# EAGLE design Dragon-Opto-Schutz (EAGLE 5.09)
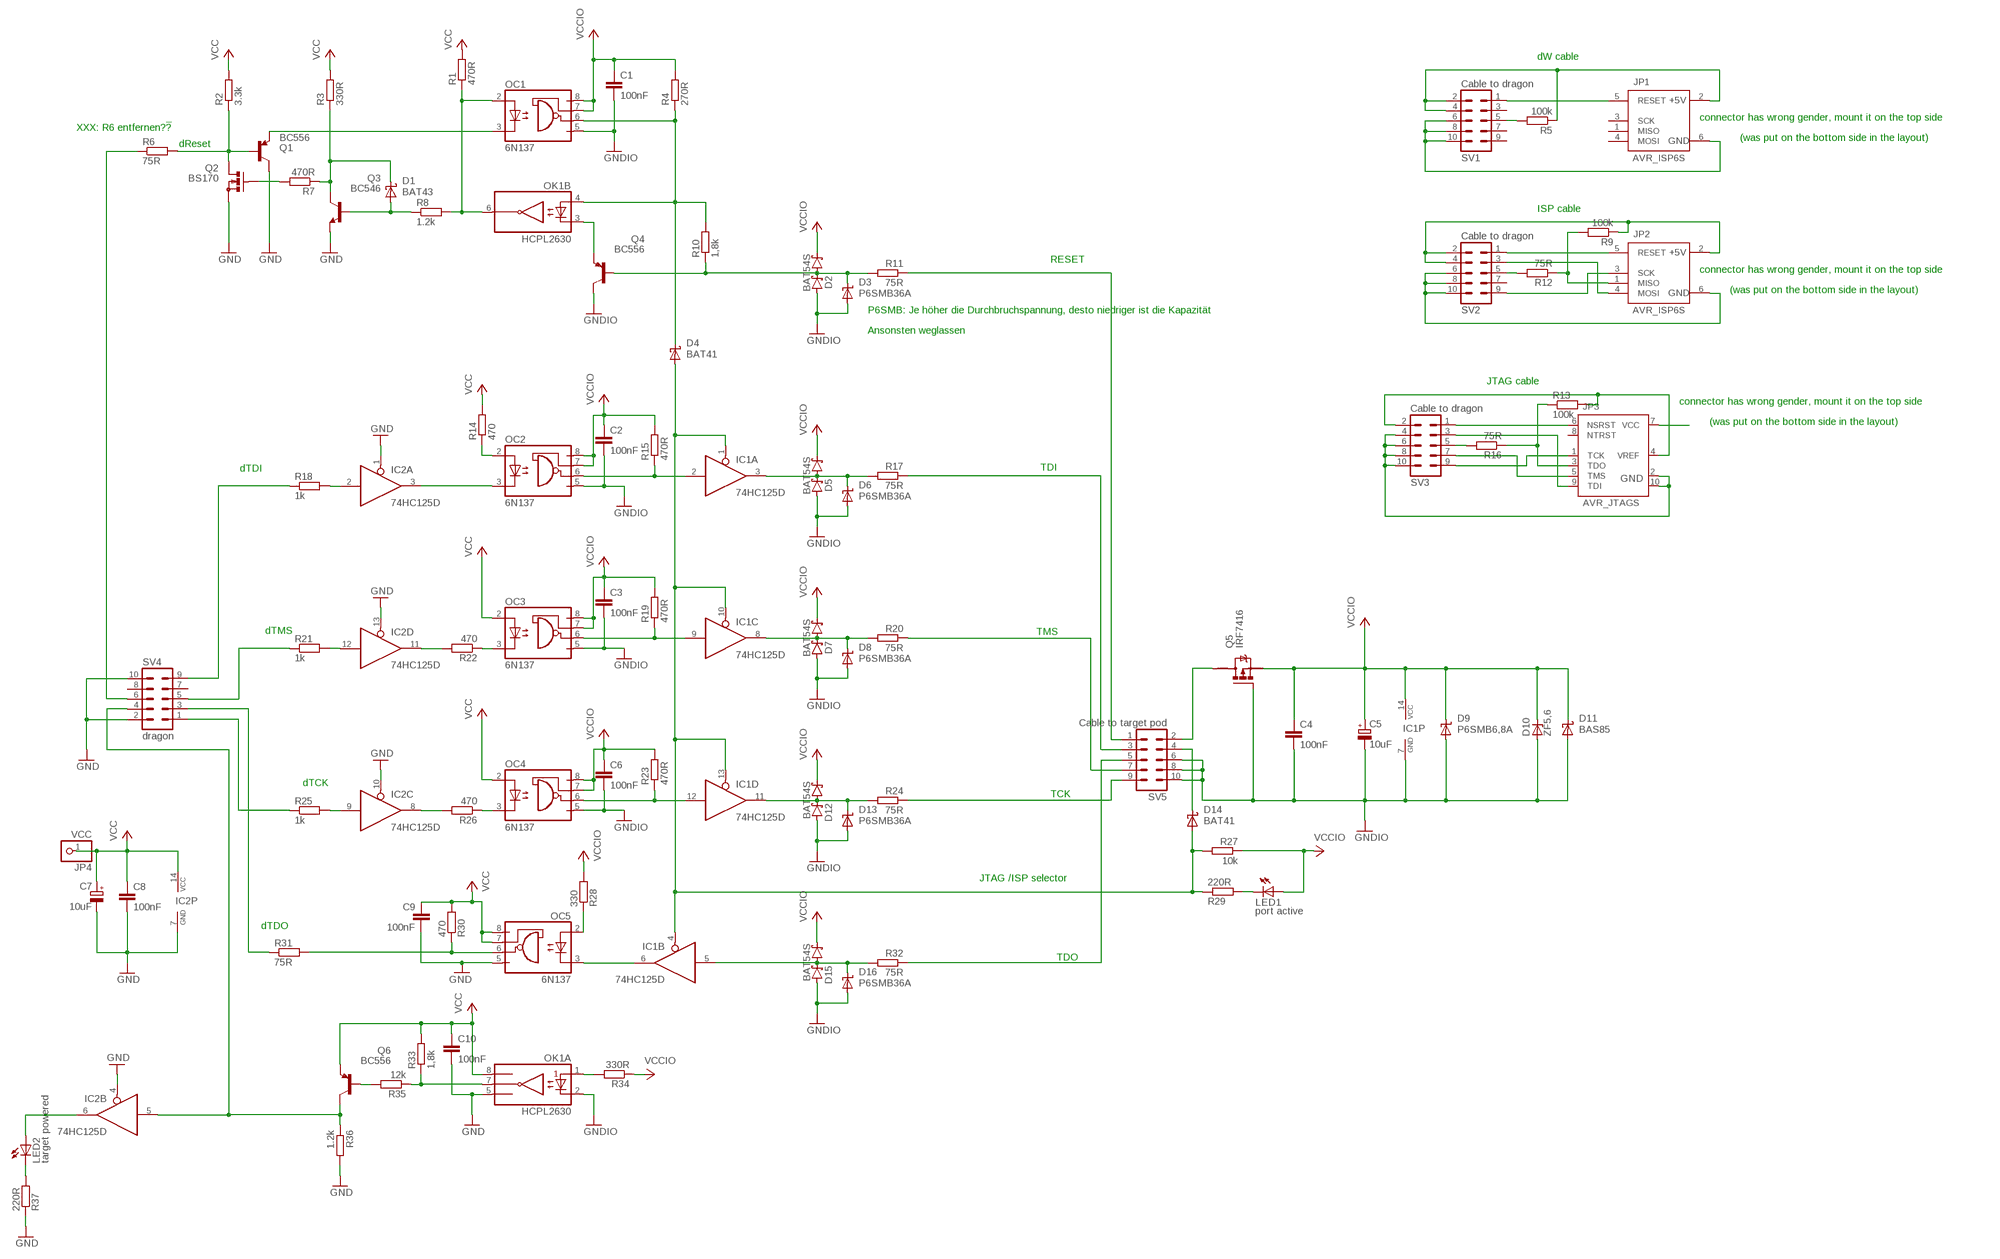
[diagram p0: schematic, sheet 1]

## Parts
C1  100nF  C-EUC0805  [C0805]
C2  100nF  C-EUC0805  [C0805]
C3  100nF  C-EUC0805  [C0805]
C4  100nF  C-EUC0805  [C0805]
C5  10uF  CPOL-EUB  [PANASONIC_B]
C6  100nF  C-EUC0805  [C0805]
C7  10uF  CPOL-EUB  [PANASONIC_B]
C8  100nF  C-EUC0805  [C0805]
C9  100nF  C-EUC0805  [C0805]
C10  100nF  C-EUC0805  [C0805]
D1  BAT43  SCHOTTKY-MINIMELF  [MINIMELF]
D2  BAT54S  DUAL_SCHOTTKY_CACASOT23  [SOT23]
D3  P6SMB36A  P6SMBXXA  [SMB]
D4  BAT41  SCHOTTKY-MINIMELF  [MINIMELF]
D5  BAT54S  DUAL_SCHOTTKY_CACASOT23  [SOT23]
D6  P6SMB36A  P6SMBXXA  [SMB]
D7  BAT54S  DUAL_SCHOTTKY_CACASOT23  [SOT23]
D8  P6SMB36A  P6SMBXXA  [SMB]
D9  P6SMB6,8A  P6SMBXXA  [SMB]
D10  ZF5,6  ZENER-SMD  [MINIMELF]
D11  BAS85  SCHOTTKY-SOD80  [SOD80C]
D12  BAT54S  DUAL_SCHOTTKY_CACASOT23  [SOT23]
D13  P6SMB36A  P6SMBXXA  [SMB]
D14  BAT41  SCHOTTKY-MINIMELF  [MINIMELF]
D15  BAT54S  DUAL_SCHOTTKY_CACASOT23  [SOT23]
D16  P6SMB36A  P6SMBXXA  [SMB]
IC1  74HC125D  [SO14]
IC2  74HC125D  [SO14]
JP1  AVR_ISP6S  [LEISTE_2X03]
JP2  AVR_ISP6S  [LEISTE_2X03]
JP3  AVR_JTAGS  [LEISTE_2X05]
JP4  VCC  PINHD-1X1  [1X01]
LED1  port active  LED3MM  [LED3MM]
LED2  target powered  LED3MM  [LED3MM]
OC1  6N137  [DIL08]
OC2  6N137  [DIL08]
OC3  6N137  [DIL08]
OC4  6N137  [DIL08]
OC5  6N137  [DIL08]
OK1  HCPL2630  [DIL08]
Q1  BC556  [TO92-EBC]
Q2  BS170  [SOT54E]
Q3  BC546  BC546B  [TO92-EBC]
Q4  BC556  [TO92-EBC]
Q5  IRF7416  P-MOSFET-SO8  [SO-08]
Q6  BC556  [TO92-EBC]
R1  470R  R-EU_R1206  [R1206]
R2  3.3k  R-EU_R0805  [R0805]
R3  330R  R-EU_R1206  [R1206]
R4  270R  R-EU_R1206  [R1206]
R5  100k  R-EU_R0805  [R0805]
R6  75R  R-EU_R1206  [R1206]
R7  470R  R-EU_R1206  [R1206]
R8  1.2k  R-EU_R0805  [R0805]
R9  100k  R-EU_R0805  [R0805]
R10  1,8k  R-EU_R0805  [R0805]
R11  75R  R-EU_R1206  [R1206]
R12  75R  R-EU_R1206  [R1206]
R13  100k  R-EU_R0805  [R0805]
R14  470  R-EU_R1206  [R1206]
R15  470R  R-EU_R1206  [R1206]
R16  75R  R-EU_R1206  [R1206]
R17  75R  R-EU_R1206  [R1206]
R18  1k  R-EU_R0805  [R0805]
R19  470R  R-EU_R1206  [R1206]
R20  75R  R-EU_R1206  [R1206]
R21  1k  R-EU_R0805  [R0805]
R22  470  R-EU_R1206  [R1206]
R23  470R  R-EU_R1206  [R1206]
R24  75R  R-EU_R1206  [R1206]
R25  1k  R-EU_R0805  [R0805]
R26  470  R-EU_R1206  [R1206]
R27  10k  R-EU_R0805  [R0805]
R28  330  R-EU_R1206  [R1206]
R29  220R  R-EU_R1206  [R1206]
R30  470  R-EU_R1206  [R1206]
R31  75R  R-EU_R1206  [R1206]
R32  75R  R-EU_R1206  [R1206]
R33  1,8k  R-EU_R0805  [R0805]
R34  330R  R-EU_R1206  [R1206]
R35  12k  R-EU_R0805  [R0805]
R36  1.2k  R-EU_R0805  [R0805]
R37  220R  R-EU_R1206  [R1206]
SV1  Cable to dragon  MA05-2  [MA05-2]
SV2  Cable to dragon  MA05-2  [MA05-2]
SV3  Cable to dragon  MA05-2  [MA05-2]
SV4  dragon  MA05-2  [MA05-2]
SV5  Cable to target pod  MA05-2  [MA05-2]

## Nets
GND: C7.- C8.2 C9.2 C10.2 IC2.1(A:OE) IC2.4(B:OE) IC2.7(P:GND) IC2.10(C:OE) IC2.13(D:OE) OC5.5(GND) OK1.5(A:GND) Q1.C Q2.S Q3.E R36.2 R37.1 SV4.2 SV4.10
GNDIO: C1.2 C2.2 C3.2 C4.2 C5.- C6.2 D2.1(A) D3.A D5.1(A) D6.A D7.1(A) D8.A D9.A D10.A D11.A D12.1(A) D13.A D15.1(A) D16.A IC1.7(P:GND) OC1.5(GND) OC2.5(GND) OC3.5(GND) OC4.5(GND) OK1.2(A:C1) Q4.C Q5.4(G) SV5.6 SV5.8 SV5.10
JT_TCK: R24.1 SV5.9
JT_TDO: R32.1 SV5.5
JT_TMS: R20.1 SV5.7
MISO_TDO: OC5.6(VO) R30.1 R31.2
MOSI_TDI: IC2.3(A:O) OC2.3(C)
N$1: Q5.5(D) SV5.2
N$2: IC2.2(A:I) R18.2
N$3: IC2.12(D:I) R21.2
N$4: IC2.9(C:I) R25.2
N$5: LED2.K(C) R37.2
N$6: JP1.2(+5V) R5.1 SV1.2 SV1.4
N$7: D2.3(AC) D3.C Q4.B R10.1 R11.2
N$8: R17.1 SV5.3
N$9: IC2.6(B:O) LED2.A
N$10: D4.C OC1.6(VO) OK1.4(B:A2) R4.1 R10.2
N$11: LED1.K(C) R29.2
N$12: D14.C SV5.4
N$13: R6.1 SV4.6
N$14: R11.1 SV5.1
N$15: OK1.1(A:A1) R34.2
N$16: R25.1 SV4.1
N$17: JP2.2(+5V) R9.1 SV2.2 SV2.4
N$18: JP2.6(GND) SV2.6 SV2.8 SV2.10
N$19: R18.1 SV4.9
N$20: R21.1 SV4.5
N$21: R31.1 SV4.3
N$22: JP3.4(VREF) R13.2 SV3.2
N$23: JP3.2(GND) JP3.10(GND) SV3.4 SV3.6 SV3.8 SV3.10
N$24: JP3.3(TDO) R13.1 R16.1
N$25: R16.2 SV3.5
N$26: JP3.6(NSRST) SV3.1
N$27: JP3.9(TDI) SV3.3
N$28: JP3.5(TMS) SV3.7
N$29: JP3.1(TCK) SV3.9
N$30: JP2.3(SCK) SV2.9
N$31: JP2.4(MOSI) SV2.3
N$32: JP2.1(MISO) R9.2 R12.1
N$33: R12.2 SV2.5
N$34: JP2.5(RESET) SV2.1
N$35: D4.A D14.A IC1.1(A:OE) IC1.4(B:OE) IC1.10(C:OE) IC1.13(D:OE) R27.2 R29.1
N$36: JP1.6(GND) SV1.6 SV1.8 SV1.10
N$37: R5.2 SV1.5
N$38: OC5.2(A) R28.1
N$39: OC2.2(A) R14.1
N$40: IC1.2(A:I) OC2.6(VO) R15.1
N$41: JP1.5(RESET) SV1.1
N$42: JP3.7(VCC)
N$43: IC1.9(C:I) OC3.6(VO) R19.1
N$45: IC1.12(D:I) OC4.6(VO) R23.1
N$46: D5.3(AC) D6.C IC1.3(A:O) R17.2
N$47: D7.3(AC) D8.C IC1.8(C:O) R20.2
N$48: D12.3(AC) D13.C IC1.11(D:O) R24.2
N$49: D15.3(AC) D16.C IC1.5(B:I) R32.2
N$50: IC1.6(B:O) OC5.3(C)
N$51: OK1.7(A:VO1) R33.1 R35.1
N$52: Q6.B R35.2
N$53: OC1.3(C) Q1.E
N$54: D1.A Q3.B R8.1
N$55: D1.C Q3.C R3.1 R7.1
N$56: Q2.G R7.2
N$57: Q1.B Q2.D R2.1 R6.2
N$58: IC2.8(C:O) R26.2
N$59: OC1.2(A) OK1.6(B:VO2) R1.1 R8.2
N$60: IC2.5(B:I) Q6.C R36.1 SV4.4
N$61: OK1.3(B:C2) Q4.E
N$62: OC4.3(C) R26.1
N$63: IC2.11(D:O) R22.2
N$64: OC3.3(C) R22.1
VCC: C7.+ C8.1 C9.1 C10.1 IC2.14(P:VCC) JP4.1 OC3.2(A) OC4.2(A) OC5.7(VE) OC5.8(VCC) OK1.8(A:VCC) Q6.E R1.2 R2.2 R3.2 R14.2 R30.2 R33.2
VCCIO: C1.1 C2.1 C3.1 C4.1 C5.+ C6.1 D2.2(C) D5.2(C) D7.2(C) D9.C D10.C D11.C D12.2(C) D15.2(C) IC1.14(P:VCC) LED1.A OC1.7(VE) OC1.8(VCC) OC2.7(VE) OC2.8(VCC) OC3.7(VE) OC3.8(VCC) OC4.7(VE) OC4.8(VCC) Q5.1(S) R4.2 R15.2 R19.2 R23.2 R27.1 R28.2 R34.1
Unconnected: JP1.1(MISO) JP1.3(SCK) JP1.4(MOSI) JP3.8(NTRST) Q5.2(S) Q5.3(S) Q5.6(D) Q5.7(D) Q5.8(D) SV1.3 SV1.7 SV1.9 SV2.7 SV4.7 SV4.8

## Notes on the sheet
- dW cable
- connector has wrong gender, mount it on the top side
- XXX: R6 entfernen?!?
- (was put on the bottom side in the layout)
- dReset
- ISP cable
- RESET
- connector has wrong gender, mount it on the top side
- (was put on the bottom side in the layout)
- P6SMB: Je höher die Durchbruchspannung, desto niedriger ist die Kapazität
- Ansonsten weglassen
- JTAG cable
- connector has wrong gender, mount it on the top side
- (was put on the bottom side in the layout)
- dTDI | TDI
- dTMS | TMS
- dTCK
- TCK
- JTAG /ISP selector
- dTDO
- TDO

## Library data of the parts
C1-C4 C6 C8-C10 = thomas4:C-EU: CAPACITOR, European symbol
C5 C7 = thomas4:CPOL-EU: POLARIZED CAPACITOR, European symbol
D1 D4 D11 D14 = 11my-ICs:SCHOTTKY-
D2 D5 D7 D12 D15 = Thomas2:DUAL_SCHOTTKY_CACA: 2 Diodes - Cathode-Anode|Cathode-Anode
D3 D6 D8 D9 D13 D16 = 11my-ICs:P6SMBXXA: Suppressor diode
D10 = 11my-ICs:ZENER-SMD: Z DIODE
IC1 IC2 = thomas-74:74*125: Quad bus BUFFER, 3-state
JP1 JP2 = 11my-AVR:AVR_ISP6: ISP (In System Programming) Stecker fr AVRs ber diesen Anschlu kann ein AVR mit einem Standard ISP-Kabel direkt an einen Parallelport des PCs angeschlossen und programmiert werden.
JP3 = 11my-AVR:AVR_JTAG: AVR JTAG Adapter Zum Programmieren/Simulieren von AVRs in der Schaltung
JP4 = pinhead:PINHD-1X1: PIN HEADER
LED1 LED2 = led:LED: LED
OC1-OC5 = thomas5:6N137: MOTOROLA OPTO COUPLER
OK1 = optocoupler:HCPL2630: HEWLETT PACKARD OPTO COUPLER
Q1 Q4 Q6 = transistor-pnp:BC556*: PNP Transistror
Q2 = transistor-small-signal:BS170: N-CHANNEL MOS FET
Q3 = transistor-npn:BC546*: NPN Transistor
Q5 = transistor-power:P-MOSFET-SO8: P-Channel MOSFET Example: FDS4435A; P-Channel Logic Level PowerTrench® MOSFET FDS4465; P-Channel 1.8V Specified PowerTrench® MOSFET Source: www.fairchildsemi.com
R1-R26 R28-R37 = rcl:R-EU_: RESISTOR, European symbol
R27 = thomas4:R-EU_
SV1-SV5 = con-lstb:MA05-2: PIN HEADER

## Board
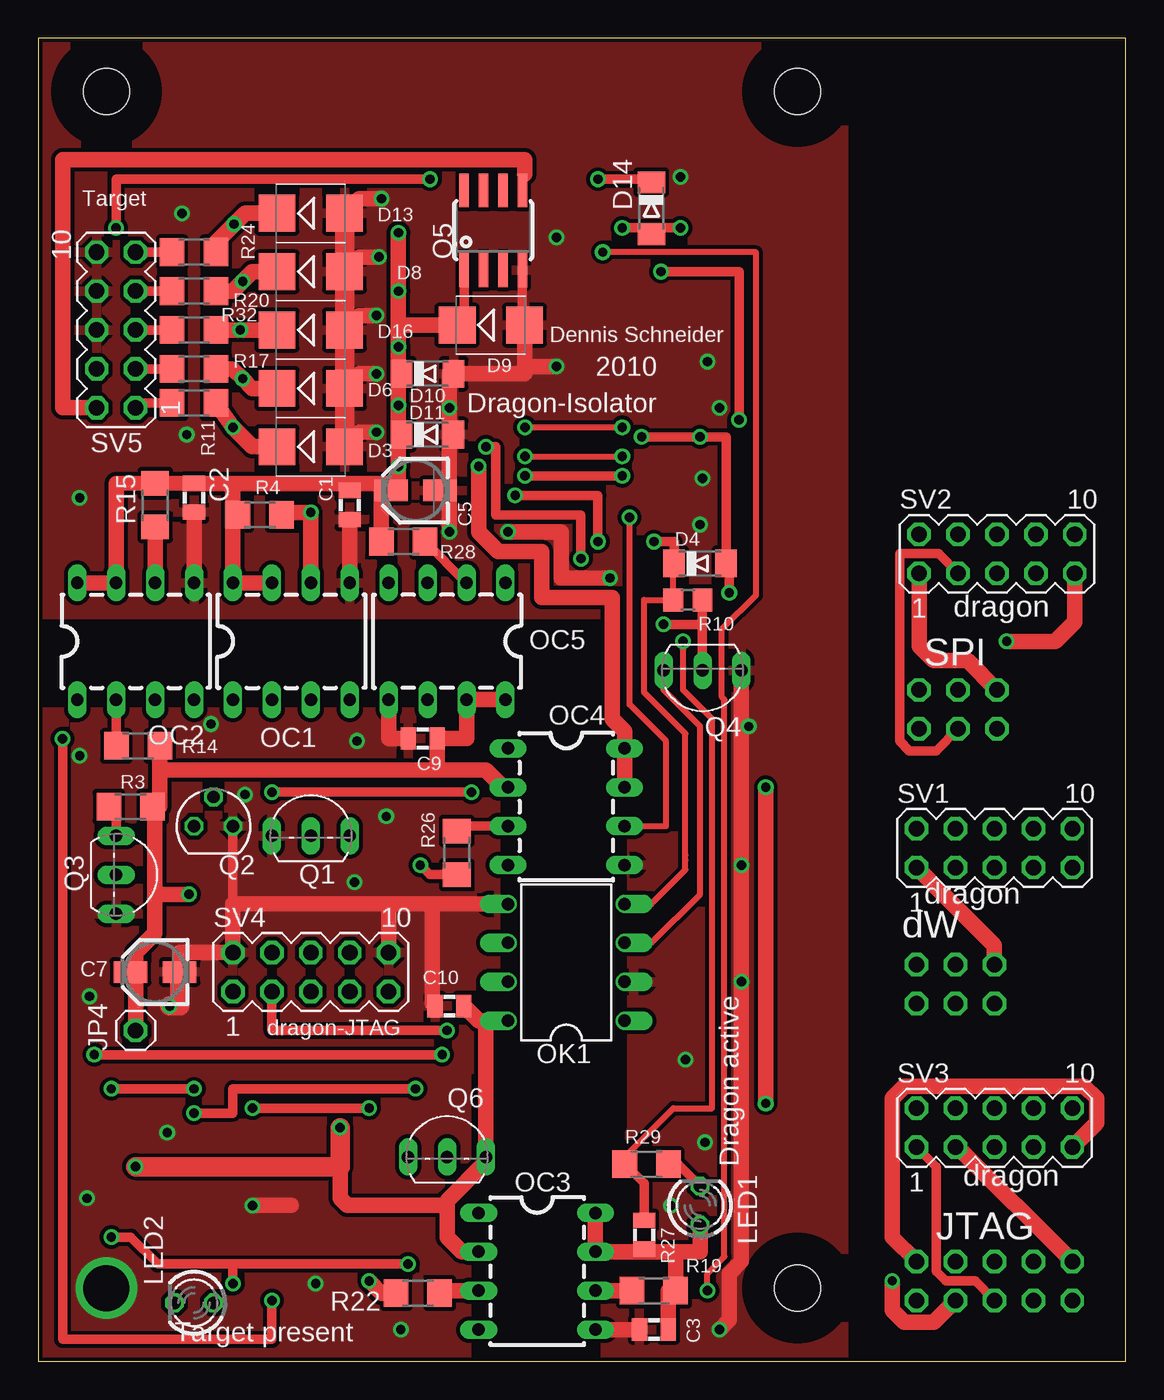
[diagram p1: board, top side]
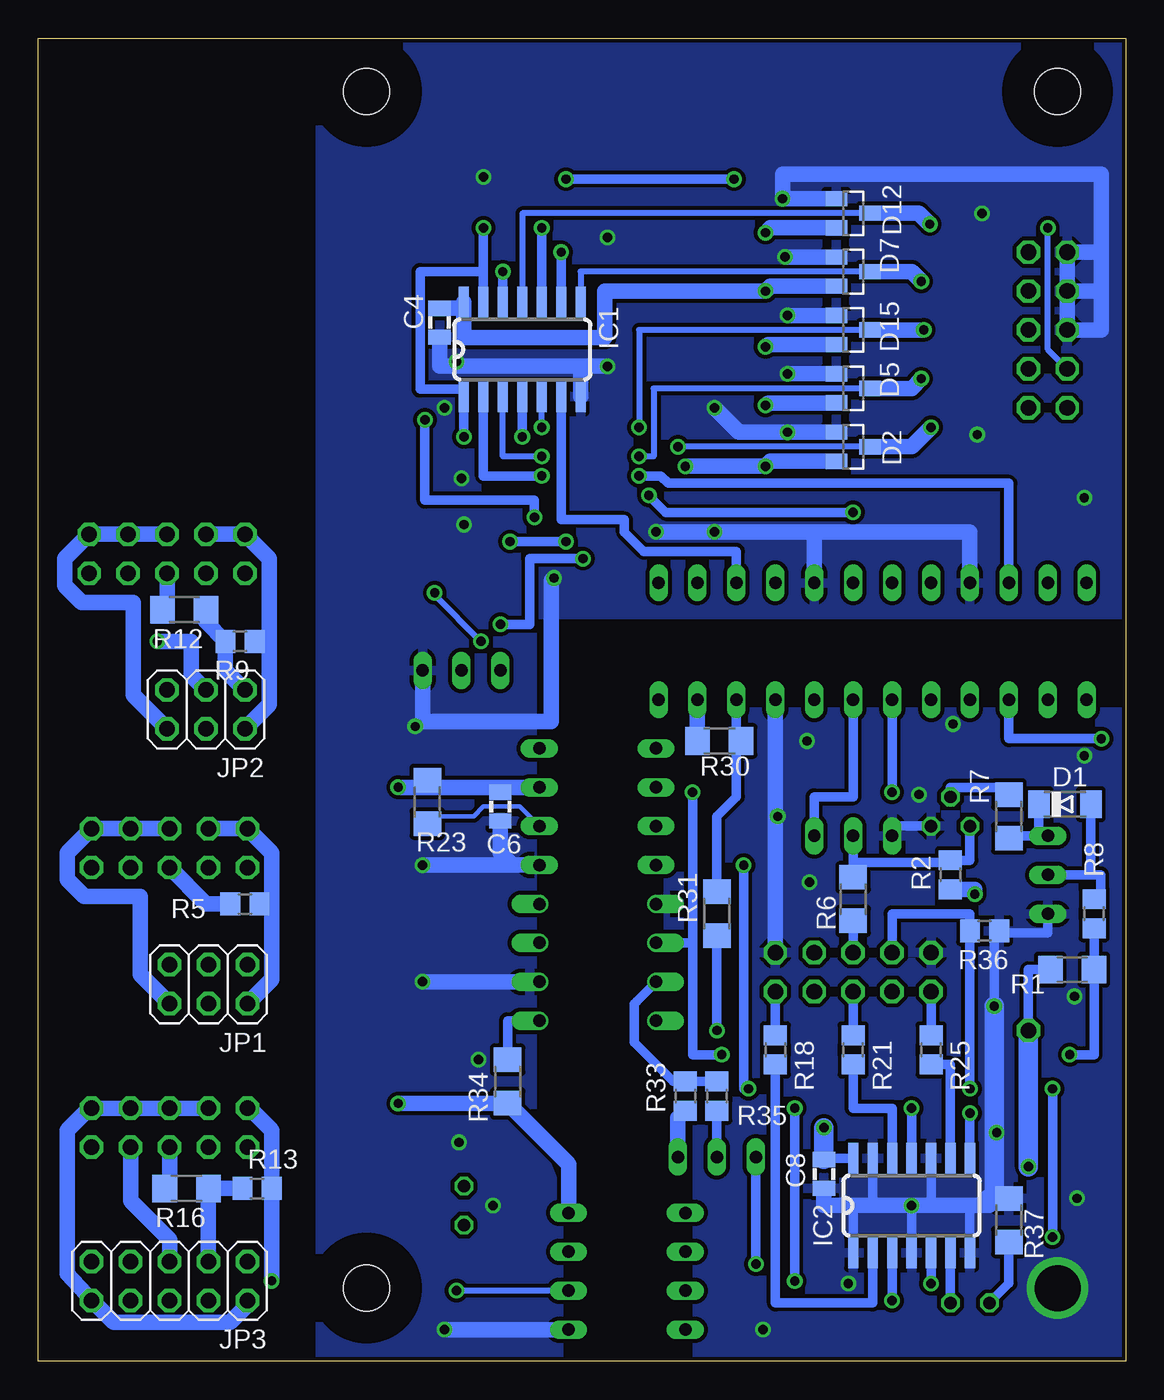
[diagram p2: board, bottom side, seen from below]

Size 70.95 x 86.35 mm. Coordinates in mm from the lower left corner, seen from the top.
Outline: 0,0 70.95,0 70.95,86.35 0,86.35 0,0
Copper layers (1+2*15+16): Top 0.035mm / dielectric 0.36mm / layer 2 0.018mm / dielectric 0.71mm / layer 15 0.018mm / dielectric 0.36mm / Bottom 0.035mm
Design rules "q-print.info": minimum track width 6mil, minimum drill 0.3mm, track to track 6mil, track to pad 6mil, pad to pad 6mil, via to via 6mil, smd to smd 6mil, copper to edge 8mil, drill to drill 10mil, minimum pad ring 8mil, minimum via ring 8mil, stop-mask expansion 4mil, vias tented up to drill 16mil, thermal gap 10mil
Holes 3 mm at 49.53,82.87 4.45,82.87 49.53,4.76
tRestrict: area 1.6,80 to 7.3,85.7; area 46.7,80 to 52.4,85.7; area 46.7,1.9 to 52.4,7.6
bRestrict: area 1.6,80 to 7.3,85.7; area 46.7,80 to 52.4,85.7; area 46.7,1.9 to 52.4,7.6

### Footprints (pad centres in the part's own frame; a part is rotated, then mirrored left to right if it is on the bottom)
C0805 = smd 0.991 x 1.448: 1 -0.94,0; 2 0.94,0
PANASONIC_B = smd 2.2 x 1.4: + 1.6,0; - -1.6,0
MINIMELF = smd 1.4 x 1.8: A 1.7,0; C -1.7,0
SOT23 = smd 1 x 1.4: 1 -0.95,-1.1; 2 0.95,-1.1; 3 0,1.1
SMB = smd 2.4 x 2.4: A 2.2,0; C -2.2,0
SOD80C = smd 1.4 x 1.8: A 1.7,0; C -1.7,0
SO14 = smd 0.66 x 2.032: 1 -3.81,-3.073; 2 -2.54,-3.073; 3 -1.27,-3.073; 4 0,-3.073; 5 1.27,-3.073; 6 2.54,-3.073; 7 3.81,-3.073; 8 3.81,3.073; 9 2.54,3.073; 10 1.27,3.073; 11 0,3.073; 12 -1.27,3.073; 13 -2.54,3.073; 14 -3.81,3.073
LEISTE_2X03 = drill 1.016 octagon: 1 -2.54,-1.27; 2 -2.54,1.27; 3 0,-1.27; 4 0,1.27; 5 2.54,-1.27; 6 2.54,1.27
LEISTE_2X05 = drill 1.016 octagon: 1 -5.08,-1.27; 2 -5.08,1.27; 3 -2.54,-1.27; 4 -2.54,1.27; 5 0,-1.27; 6 0,1.27; 7 2.54,-1.27; 8 2.54,1.27; 9 5.08,-1.27; 10 5.08,1.27
1X01 = drill 1.016 octagon: 1 0,0
LED3MM = drill 0.813 octagon: A -1.27,0; K 1.27,0
DIL08 = drill 0.813 long: 1 -3.81,-3.81; 2 -1.27,-3.81; 3 1.27,-3.81; 4 3.81,-3.81; 5 3.81,3.81; 6 1.27,3.81; 7 -1.27,3.81; 8 -3.81,3.81
DIL08' = drill 0.813 offset: 1 -3.81,-3.81; 2 -1.27,-3.81; 3 1.27,-3.81; 4 3.81,-3.81; 5 3.81,3.81; 6 1.27,3.81; 7 -1.27,3.81; 8 -3.81,3.81
TO92-EBC = drill 0.813 long: B 0,-1.27; C -2.54,-1.27; E 2.54,-1.27
SOT54E = drill 0.813 octagon: D -1.27,0; G 0,1.905; S 1.27,0
SO-08 = smd 0.6 x 2.2: 1 -1.905,-2.6; 2 -0.635,-2.6; 3 0.635,-2.6; 4 1.905,-2.6; 5 1.905,2.6; 6 0.635,2.6; 7 -0.635,2.6; 8 -1.905,2.6
R1206 = smd 1.6 x 1.803: 1 -1.422,0; 2 1.422,0
R0805 = smd 1.3 x 1.5: 1 -0.95,0; 2 0.95,0
R0805' = smd 0.991 x 1.448: 1 -0.94,0; 2 0.94,0
MA05-2 = drill 1.016 octagon: 1 -5.08,-1.27; 2 -5.08,1.27; 3 -2.54,-1.27; 4 -2.54,1.27; 5 0,-1.27; 6 0,1.27; 7 2.54,-1.27; 8 2.54,1.27; 9 5.08,-1.27; 10 5.08,1.27

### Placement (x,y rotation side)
C1  20.32,55.88 270 top
C2  10.16,56.36 270 top
C3  40.16,2.06 180 top
C4  44.77,67.79 270 bottom
C5  24.61,56.83 180 top
C6  40.8,36.2 270 bottom
C7  7.62,25.4 180 top
C8  19.68,12.22 270 bottom
C9  25.08,40.64 180 top
C10  26.83,23.18 180 top
D1  3.97,36.35 0 bottom
D2  17.78,59.69 270 bottom
D3  17.78,59.69 0 top
D4  43.18,52.07 0 top
D5  17.78,63.5 270 bottom
D6  17.78,63.5 0 top
D7  17.78,71.12 270 bottom
D8  17.78,71.12 0 top
D9  29.53,67.63 0 top
D10  25.4,64.45 0 top
D11  25.4,60.48 0 top
D12  17.78,74.93 270 bottom
D13  17.78,74.93 0 top
D14  40.01,75.25 270 top
D15  17.78,67.31 270 bottom
D16  17.78,67.31 0 top
IC1  39.37,66.04 0 bottom
IC2  13.97,10.16 0 bottom
JP1  59.85,24.61 180 bottom
JP2  60.01,42.55 180 bottom
JP3  62.39,5.24 180 bottom
JP4  6.35,21.59 90 top
LED1  43.18,10.16 90 top
LED2  10.16,3.81 180 top
OC1  16.51,46.99 0 top
OC2  6.35,46.99 0 top
OC3  32.54,5.87 270 top
OC4  34.45,36.2 270 top
OC5  26.67,46.99 180 top
OK1  HCPL2630  [DIL08']  34.45,26.04 90 top
Q1  17.78,35.56 0 top
Q2  11.43,34.92 0 top
Q3  6.35,31.75 270 top
Q4  43.34,43.82 180 top
Q5  29.69,73.82 0 top
Q6  26.67,14.6 0 top
R1  3.49,25.56 180 bottom
R2  11.43,31.75 270 bottom
R3  6.03,36.2 0 top
R4  14.45,55.24 180 top
R5  57.47,29.85 180 bottom
R6  17.78,30.16 90 bottom
R7  7.62,35.56 90 bottom
R8  2.06,29.21 270 bottom
R9  57.78,46.99 180 bottom
R10  42.39,49.69 180 top
R11  10.16,62.55 0 top
R12  61.44,49.05 180 bottom
R13  56.67,11.27 0 bottom
R14  6.51,40.16 0 top
R15  7.62,55.88 90 top
R16  61.28,11.27 180 bottom
R17  10.16,64.77 0 top
R18  22.86,20.32 270 bottom
R19  40.16,4.6 0 top
R20  10.16,69.85 0 top
R21  17.78,20.32 270 bottom
R22  24.77,4.45 180 top
R23  45.56,36.51 90 bottom
R24  10.16,72.39 0 top
R25  12.7,20.32 270 bottom
R26  27.31,33.18 270 top
R27  10k  [R0805']  39.53,8.26 90 top
R28  23.81,53.5 180 top
R29  39.69,12.86 0 top
R30  26.51,40.48 180 bottom
R31  26.67,29.21 90 bottom
R32  10.16,67.31 0 top
R33  28.73,17.3 270 bottom
R34  40.32,18.26 90 bottom
R35  26.67,17.3 270 bottom
R36  9.21,28.1 0 bottom
R37  7.62,9.21 270 bottom
SV1  62.39,33.5 0 top
SV2  62.55,52.7 0 top
SV3  62.39,15.24 0 top
SV4  17.78,25.4 0 top
SV5  5.08,67.31 90 top

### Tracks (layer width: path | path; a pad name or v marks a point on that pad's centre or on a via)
GND  (via drill 0.61, 3)
  Top 0.61: 12.7,29.84 Q2.S
  Top 1.016: 22.86,29.84 12.7,29.84 SV4.2 9.22,26.67 C7.- | 22.86,29.84 SV4.10 | C9.2 22.86,40.64 OC5.5 | v13.97,10.16 16.51,10.16 | 22.86,29.84 25.72,29.84 | 25.72,29.84 OK1.5 | C10.2 25.72,23.35 25.72,29.84
  Top 1.27: v8.57,23.18 9.22,23.18 C7.-
  Bottom 0.61: 12.7,10.16 IC2.10 | IC2.7 10.16,10.16 | 16.51,10.16 IC2.13 | 17.78,10.16 IC2.1 | v13.97,10.16 IC2.4 | R37.1 8.89,10.62 8.89,10.16 | Q2.S 15.24,34.92 Q1.C | v8.57,23.18 8.57,27.94 | 8.57,27.94 5.08,27.94 Q3.E | R36.2 8.57,28.1 8.57,27.94
  Bottom 1.016: 8.89,10.16 10.16,10.16 12.7,10.16 v13.97,10.16 16.51,10.16 17.78,10.16 19.68,10.16 C8.2 | SV4.10 OC5.5
  Bottom 1.27: 8.89,10.62 8.57,10.62 v8.57,23.18
  other vias: 23.65,2.06 20.64,31.27 18.1,5.08 11.27,41.59 3.33,23.81 3.18,10.64 8.41,14.92 13.49,36.99 22.7,35.56 2.7,39.53 4.45,4.76 20.8,40.48
  pour Bottom (isolate 0.254): 0,0 27.94,0 27.94,19.05 29.84,19.05 29.84,42.39 0,42.39
  pour Top (isolate 0.254): 0,0 27.94,0 27.94,19.05 29.84,19.05 29.84,42.39 0,42.39
GNDIO  (via drill 0.61)
  Top 0.61: Q5.4 31.59,68.58 31.73,68.58 D9.A
  Top 1.016: OC2.5 C2.2 | C1.2 | OC1.5 C1.2 | OC3.5 C3.2 | C3.2 | v22.38,75.88 20.93,75.88 D13.A | v22.23,72.07 20.93,72.07 D8.A | v22.07,68.26 20.93,68.26 D16.A | v22.07,64.45 20.93,64.45 D6.A | v22.07,60.64 20.93,60.64 D3.A | v26.83,54.13 26.83,56.52 | 31.73,64.93 31.73,64.45 D10.A 26.83,64.45 v26.83,62.23 26.83,60.96 | 31.73,64.93 D9.A | 26.83,56.52 C5.- | 26.83,56.52 26.83,60.96 | D11.A 27.1,60.69 26.83,60.96 | 45.88,40.16 v45.88,32.38 v45.88,24.77 45.88,6.51 45.09,5.71 45.09,2.7 v44.45,2.06 | 45.88,40.16 | 45.88,40.16 Q4.C | v30.64,54.13 34.13,54.13 34.13,51.12 v37.31,51.12 | 31.73,64.93 v33.81,64.93
  Top 1.27: D13.A D8.A D16.A D6.A D3.A
  Bottom 1.016: OC2.5 10.16,54.13 20.32,54.13 | 20.32,54.13 OC1.5 | D12.1 v22.38,75.88 22.38,77.47 1.59,77.47 1.59,72.39 | D7.1 v22.22,72.07 v22.23,72.07 | D15.1 v22.06,68.26 v22.07,68.26 | D5.1 v22.06,64.45 v22.07,64.45 | D2.1 v22.06,60.64 v22.07,60.64 25.24,60.64 v26.83,62.23 | SV5.8 SV5.6 1.59,67.31 1.59,69.85 | 1.59,69.85 SV5.8 | 20.32,54.13 v26.83,54.13 v30.64,54.13 | OC3.5 v44.45,2.06 | v45.88,24.77 OK1.2 | v45.88,24.77 | C6.2 40.8,33.18 40.01,32.38 OC4.5 v45.88,32.38 | v37.31,51.12 37.47,50.96 37.47,41.75 45.88,41.75 Q4.C | 35.56,64.94 IC1.7 | 35.56,64.94 33.81,64.94 v33.81,64.93 | 35.56,64.94 44.77,64.94 C4.2 | 1.59,72.39 1.59,69.85 | 1.59,72.39 SV5.10 SV5.8
  other vias: 43.5,14.29 41.28,10.16 46.36,41.43 9.68,60.48 33.81,73.34 42.23,19.69 41.91,77.31 43.18,54.61 44.45,62.23 43.34,57.63 43.66,65.25 2.7,56.36 9.37,74.93
  pour Bottom (isolate 0.254): 36.99,0 52.55,0 52.55,86.2 0.16,86.36 0,79.85 0,48.74 38.74,48.74 38.73,15.24 36.99,10.95
  pour Top (isolate 0.254): 52.55,0 52.55,86.2 0.16,86.36 0,79.85 0,48.74 38.74,48.74 38.73,15.24 36.99,10.95 36.99,0
JT_TCK
  Top 0.61: SV5.9 R24.1
JT_TDO
  Top 0.61: SV5.5 R32.1
JT_TMS
  Top 0.61: SV5.7 R20.1
MISO_TDO
  Bottom 0.61: 26.19,30.8 26.67,30.8 R31.2 26.67,35.56 25.4,36.83 25.4,40.17 R30.1 25.4,40.79 OC5.6
MOSI_TDI  (via drill 0.61)
  Top 0.61: v15.24,3.97 15.24,1.43 1.59,1.43 v1.59,40.64
  Bottom 0.61: v15.24,3.97 IC2.3 | v1.59,40.64 7.62,40.64 OC2.3
N$1
  Top 0.61: 31.75,77.47 31.59,77.47 Q5.5
  Top 1.016: SV5.2 1.59,62.23 1.59,78.42 31.75,78.42 31.75,77.47
N$2
  Bottom 0.61: R18.2 22.86,3.81 16.51,3.81 IC2.2
N$3
  Bottom 0.61: IC2.12 15.24,16.51 17.78,16.51 R21.2
N$4
  Bottom 0.61: IC2.9 11.43,19.37 R25.2
N$5
  Bottom 0.61: LED2.K 7.62,5.08 R37.2
N$6
  Bottom 1.016: SV1.4 SV1.2 55.72,33.18 55.72,29.84 | 55.72,29.84 R5.1 | JP1.2 55.72,24.92 55.72,29.84
N$7  (via drill 0.61)
  Top 0.406: R10.1 43.18,49.84
  Top 0.61: Q4.B 43.34,48.1 | 43.34,48.1 R10.1 | v35.4,52.39 35.4,55.24 29.84,55.24 29.84,59.69 v29.21,59.69 | v40.8,48.1 43.34,48.1
  Top 1.016: R11.2 12.69,60.96 v12.7,60.96 13.97,59.69 D3.C
  Bottom 0.406: D2.3 v29.21,59.69
  Bottom 0.61: v35.4,52.39 38.89,52.39 38.89,48.1 v40.8,48.1 | Q4.B
  Bottom 1.016: D2.3 13.97,59.69 v12.7,60.96
N$8
  Top 0.61: SV5.3 R17.1
N$9
  Bottom 0.61: LED2.A IC2.6
N$10  (via drill 0.61)
  Top 0.406: D4.C 41.44,52.03 R10.2 39.53,49.69 39.53,43.66 42.23,40.96 42.23,33.02 42.23,32.7 42.23,32.07 40.01,29.84 OK1.4
  Top 0.61: v31.11,56.52 36.51,56.52 v36.51,53.5 | v40.16,53.5 41.48,53.5 D4.C
  Top 1.016: v17.78,55.4 15.87,55.4 R4.1 | v17.78,55.4 | v17.78,55.4 OC1.6
  Bottom 0.61: v17.78,55.4 30,55.4 v31.11,56.52 | v40.16,53.5 v36.51,53.5
N$11
  Top 0.61: LED1.K 41.75,12.86 R29.2
N$12  (via drill 0.61)
  Top 0.61: D14.C 40.01,77.15 v36.51,77.15 | v25.56,77.15 5.08,77.15 v5.08,73.98
  Bottom 0.406: SV5.4 5.08,66.04 v5.08,73.98
  Bottom 0.61: v25.56,77.15 v36.51,77.15
N$13
  Bottom 0.61: SV4.6 R6.1
N$14
  Top 0.61: SV5.1 6.67,62.55 R11.1
N$15
  Bottom 0.61: R34.2 40.32,22.23 OK1.1
N$16
  Bottom 0.61: R25.1 SV4.1
N$17
  Bottom 1.016: SV2.4 SV2.2 55.88,52.39 55.88,46.99 | 55.88,46.99 R9.1 | 55.88,46.99 55.88,42.86 JP2.2
N$18
  Bottom 1.016: SV2.6 SV2.8 SV2.10 69.22,52.39 69.22,50.64 68.1,49.53 64.77,49.53 64.77,43.5 JP2.6
N$19
  Bottom 0.61: R18.1 SV4.9
N$20
  Bottom 0.61: R21.1 SV4.5
N$21  (via drill 0.61)
  Top 0.61: SV4.3 15.24,21.59 v26.67,21.59
  Bottom 0.61: v26.67,21.59 R31.1
N$22  (via drill 0.6)
  Top 1.016: v55.72,5.24 55.72,3.33 56.52,2.54 58.42,2.54 JP3.4
  Bottom 1.016: SV3.2 57.15,16.51 55.72,15.08 R13.2 55.72,5.71 v55.72,5.24
N$23
  Bottom 1.016: SV3.4 SV3.6 SV3.8 SV3.10 67.63,16.51 68.9,15.24 69.06,15.08 69.06,5.71 JP3.10 66.04,2.54 58.42,2.54 57.31,3.65 JP3.2
N$24
  Bottom 1.016: R13.1 R16.1 JP3.3
N$25
  Bottom 1.016: R16.2 62.39,11.58 SV3.5
N$26
  Top 0.61: SV3.1 58.58,12.7 58.58,5.87 59.21,5.24 61.12,5.24 JP3.6 | JP3.6
N$27
  Top 1.016: JP3.9 60.01,13.97 SV3.3
N$28
  Bottom 1.016: JP3.5 | JP3.5 62.39,7.94 64.93,10.48 SV3.7
N$29
  Top 1.016: JP3.1 55.72,8.1 55.72,17.14 56.52,17.94 68.26,17.94 69.06,17.14 69.06,15.56 68.9,15.4 SV3.9
N$30  (via drill 0.6)
  Top 1.016: v63.18,46.99 66.36,46.99 67.63,48.26 SV2.9
  Bottom 1.016: JP2.3 60.96,44.77 60.96,46.99 v63.18,46.99
N$31
  Top 0.61: SV2.3 58.74,52.7 56.2,52.7 56.2,50.64 56.2,50.48 56.2,40.48 56.83,39.85 58.58,39.85 JP2.4 | JP2.4
N$32
  Bottom 1.016: JP2.1 58.73,45.08 R9.2 60.01,48.27 R12.1
N$33
  Bottom 1.016: SV2.5 62.55,49.54 R12.2
N$34
  Top 1.016: JP2.5 60.64,45.72 58.42,45.72 57.47,46.67 SV2.1
N$35  (via drill 0.61)
  Top 0.406: v42.07,46.99 42.07,43.81 43.97,41.91 43.97,16.51 41.43,16.51 38.27,13.34 R29.1
  Top 0.61: v38.1,73.98 v41.91,73.98 40.01,73.98 D14.A | v39.37,60.33 v43.18,60.33 44.88,60.33 D4.A 45.09,51.87 v45.09,50.16 | R29.1 39.53,11.6 R27.2
  Bottom 0.406: v42.07,46.99 45.09,50.01 v45.09,50.16
  Bottom 0.61: v38.1,73.98 IC1.10 | 41.91,71.12 IC1.13 | v39.37,60.33 IC1.4 | v43.18,60.33 IC1.1 43.18,63.44 46.04,63.44 46.04,71.12 41.91,71.12 | 41.91,71.12 v41.91,73.98
N$36
  Bottom 1.016: SV1.6 SV1.8 SV1.10 69.06,33.18 69.06,31.43 67.94,30.32 64.29,30.32 64.29,25.24 JP1.6
N$37
  Bottom 1.016: R5.2 60.01,29.84 SV1.5
N$38
  Top 0.61: OC5.2 R28.1
N$39
  Top 0.61: R14.1 OC2.2
N$40  (via drill 0.61)
  Top 0.61: v31.75,57.78 v38.1,57.78
  Top 1.016: OC2.6 R15.1
  Bottom 0.61: OC2.6 7.62,57.31 29.84,57.31 30.32,57.78 v31.75,57.78 | v38.1,57.78 41.91,57.78 IC1.2
N$41
  Top 1.016: JP1.5 62.39,27.15 61.28,28.26 59.05,30.48 SV1.1
N$43  (via drill 0.61)
  Top 0.406: v36.83,72.39 46.83,72.39 46.83,50.01 44.61,47.78 44.61,43.34 44.77,43.18 44.77,6.83 43.66,5.71 v43.66,4.6
  Top 1.016: OC3.6 R19.1
  Bottom 0.406: OC3.6 v43.66,4.6
  Bottom 0.61: v36.83,72.39 IC1.9
N$45  (via drill 0.61)
  Top 0.406: OC4.6 40.96,34.92 40.96,40.48 38.58,42.86 v38.58,55.09
  Top 0.61: v40.64,71.12 45.72,71.12 v45.72,61.44
  Bottom 0.305: OC4.6 39.53,36.2 41.91,36.2 42.53,35.57 45.88,35.57 R23.1
  Bottom 0.61: v40.64,71.12 IC1.12 | v45.72,61.44 45.72,56.2 38.58,56.2 v38.58,55.09
N$46  (via drill 0.61)
  Top 0.406: v31.75,59.05 v38.1,59.05
  Top 1.016: R17.2 12.7,64.77 v13.34,64.14 13.97,63.5 D6.C
  Bottom 0.406: D5.3 30.8,63.5 30.8,59.05 v31.75,59.05 | v38.1,59.05 40.64,59.05 IC1.3
  Bottom 1.016: D5.3 13.97,63.5 v13.34,64.14
N$47  (via drill 0.61)
  Top 1.016: R20.2 12.7,69.85 v13.34,70.48 13.97,71.12 D8.C
  Bottom 0.406: D7.3 35.56,71.12 IC1.8
  Bottom 1.016: D7.3 13.97,71.12 v13.34,70.48
N$48  (via drill 0.61)
  Top 1.016: 15.24,74.93 D13.C 13.49,74.93 v12.78,74.22 11.58,73.02 R24.2
  Bottom 0.406: D12.3 39.37,74.93 IC1.11
  Bottom 1.016: D12.3 13.49,74.93 v12.78,74.22
N$49  (via drill 0.61)
  Top 0.406: v31.75,60.96 v38.1,60.96
  Top 1.016: R32.2 v13.18,67.31 D16.C
  Bottom 0.406: D15.3 31.75,67.31 v31.75,60.96 | v38.1,60.96 IC1.5
  Bottom 1.016: v13.18,67.31 D15.3
N$50
  Bottom 0.61: OC5.3 25.4,52.86 31.43,52.86 32.7,54.13 32.7,54.93 36.83,54.93 IC1.6
N$51
  Bottom 0.61: R35.1 R33.1 | R33.1 | R33.1 28.73,18.57 | 31.91,23.5 OK1.7 | 31.91,23.5 | 31.91,23.5 32.07,23.34 32.07,20.8 29.52,18.25 R33.1
N$52
  Bottom 0.61: Q6.B R35.2 | R35.2
N$53
  Bottom 0.61: OC1.3 17.78,36.83 20.32,36.83 Q1.E
N$54
  Bottom 0.61: 2.27,31.75 Q3.B | R8.1 1.63,30.16 1.63,31.75 2.27,31.75 | 2.27,31.75 D1.A
N$55
  Top 0.61: Q3.C 5.08,35.88 R3.1
  Bottom 0.61: D1.C 5.67,34.29 Q3.C 7.62,34.29 R7.1
N$56
  Bottom 0.61: R7.2 7.62,37.47 11.43,37.47 Q2.G
N$57
  Bottom 0.61: 17.78,32.54 Q1.B | Q2.D 10.16,32.7 R2.1 11.43,32.54 17.78,32.54 | R6.2 17.78,32.54
N$58  (via drill 0.61)
  Top 0.61: v10.16,16.19 12.7,16.19 12.7,17.78 v24.61,17.78 | R26.2 25.55,31.76 v24.92,32.38
  Bottom 0.61: IC2.8 v10.16,16.19 | v24.61,17.78 24.92,17.78 v24.92,32.38
N$59  (via drill 0.61)
  Top 0.61: v3.65,20 v26.35,20 | v28.26,37.15 v15.24,37.15
  Bottom 0.61: R1.1 R8.2 | R1.1 | R1.1 2.06,20 v3.65,20 | v15.24,37.15 OC1.2 | v26.35,20 28.26,20 28.26,26.67 | 28.26,26.67 v28.26,37.15 | OK1.6 28.26,27.3 28.26,26.67
N$60  (via drill 0.61)
  Top 0.61: 12.7,6.35 v12.7,5.08 | v4.76,17.78 v10.16,17.78 | 12.7,6.35 7.78,6.35 6.03,8.1 v4.76,8.1 | 12.7,6.35 v24.13,6.35
  Bottom 0.61: SV4.4 15.24,29.21 10.16,29.21 R36.1 | v12.7,5.08 IC2.5 | R36.1 | v10.16,17.78 R36.1 | v4.76,8.1 v4.76,17.78 | v24.13,6.35 | v24.13,6.35 Q6.C
N$61
  Top 0.406: Q4.E 40.8,43.81 43.18,41.43 43.18,30.48 40.01,27.3 OK1.3
N$62
  Top 0.61: R26.1 | R26.1 27.3,34.92 OC4.3
N$63  (via drill 0.61)
  Top 0.61: v21.59,16.51 v13.97,16.51
  Top 1.016: R22.2 22.38,4.45 v21.59,5.24
  Bottom 0.61: v13.97,16.51 IC2.11 | v21.59,5.24 v21.59,16.51
N$64
  Top 1.016: OC3.3 26.35,4.6 R22.1
VCC  (via drill 0.61)
  Top 1.016: JP4.1 6.35,25.4 C7.+ 6.35,25.73 6.35,26.67 7.61,27.93 7.61,30.48 | OC5.8 OC5.7 27.94,40.64 C9.1 26.02,38.58 | 26.02,38.58 29.21,38.58 30.32,37.47 OC4.2 | 19.68,12.7 19.68,10.64 20.16,10.16 26.67,10.16 | OC3.2 27.62,7.14 26.67,8.1 26.67,10.16 | Q6.E 29.21,12.7 | 26.67,10.16 26.67,10.48 29.21,13.02 Q6.E | 7.93,38.58 26.02,38.58 | 7.93,38.58 R14.2 | 7.61,30.48 v9.84,30.48 | 7.61,30.48 7.61,36.04 R3.2 7.93,36.2 7.93,38.58 | C10.1 28.75,22.23 29.21,22.23 | 29.21,22.23 OK1.8 | Q6.E 29.21,22.23 | 29.21,22.23
  Top 1.27: v6.35,12.7 19.68,12.7 v19.68,15.24
  Bottom 0.61: IC2.14 19.68,13.23 C8.1 | R1.2 6.35,25.56 JP4.1
  Bottom 1.016: Q6.E 29.21,15.88 R33.2 | R30.2 27.94,40.64 OC5.7 | R2.2 9.84,30.8 v9.84,30.48
  Bottom 1.27: v6.35,12.7 JP4.1 | v19.68,15.24 C8.1
VCCIO  (via drill 0.61)
  Top 0.61: Q5.1 27.78,68.42 27.33,68.42 D9.C
  Top 1.016: OC2.8 OC2.7 5.08,57.3 R15.2 C2.1 12.7,57.3 | 12.7,55.24 OC1.8 OC1.7 | C1.1 | C3.1 41.1,4.6 R19.2 41.58,7.14 | 39.37,7.14 OC3.7 OC3.8 | 39.37,7.14 41.58,7.14 | v23.5,73.66 v23.5,69.85 23.5,67.63 | 23.5,64.77 v23.5,62.39 23.5,60.96 | 23.5,64.77 v23.5,66.2 23.5,67.63 | 23.5,60.96 v23.5,58.42 23.5,56.82 | 23.5,56.82 22.86,56.82 22.86,56.83 C5.+ | 23.5,67.63 D9.C | R27.1 39.37,7.32 39.37,7.14 | 41.58,7.14 43.18,7.14 LED1.A | D10.C 23.7,64.56 23.5,64.77 | D11.C 23.7,60.76 23.5,60.96 | OC4.7 OC4.8 38.26,41.12 37.47,41.91 37.47,49.85 32.86,49.85 32.86,52.86 30,52.86 28.73,54.13 v28.73,58.42 | v47.47,16.83 v47.47,37.47 | 23.5,56.82 23.03,56.81 | 20.32,57.3 12.7,57.3 | 20.32,57.3 C1.1 | 20.32,57.3 23.01,57.3 C5.+ | 12.7,55.24 R4.2 | 12.7,57.3 12.7,55.24 | R28.2 22.39,56.83 C5.+
  Bottom 1.016: D12.2 23.18,73.98 v23.5,73.66 | D7.2 23.18,70.17 v23.5,69.85 33.97,69.85 33.97,66.82 43.18,66.82 43.18,68.73 | D15.2 23.33,66.36 v23.5,66.2 | D5.2 23.33,62.55 v23.5,62.39 | D2.2 23.18,58.74 v23.5,58.42 v28.73,58.42 | v47.47,16.83 R34.1 36.35,12.87 OC3.8 | 45.72,37.47 v47.47,37.47 47.45,37.45 | 45.72,37.47 40.64,37.47 | 40.64,37.47 OC4.7 | C6.1 40.64,37.29 40.64,37.47 | 43.18,68.73 IC1.14 | 43.18,68.73 C4.1 | R23.2 45.56,37.62 45.72,37.47

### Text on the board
tNames: Target | Dennis Schneider | 2010 | Dragon-Isolator | dragon | SPI | dragon | dW | dragon-JTAG | Dragon active | dragon | JTAG | Target present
